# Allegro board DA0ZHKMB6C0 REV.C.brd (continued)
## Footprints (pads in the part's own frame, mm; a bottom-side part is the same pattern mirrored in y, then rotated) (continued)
CC0402
  custom 0.12x0.12 smd: 1(0.39,0) 2(-0.39,0)
CC0603
  rect 0.813x0.711 smd: 1(0.737,0) 2(-0.737,0)
CC0805
  rect 0.94x1.346 smd: 1(0.895,0) 2(-0.895,0)
CC1206
  rect 1.6x1.6 smd: 1(1.702,0) 2(-1.702,0)
CC1808
  rect 2.159x2.286 smd: 1(-2.349,0) 2(2.349,0)
CC3528
  rect 2.032x2.413 smd: 1(1.6,0) 2(-1.6,0)
CC7343
  rect 2.413x2.819 smd: 1(-3.2,0) 2(3.2,0)
CHOKE-DLW21S-4P
  rect 0.889x0.356 smd: 1(-0.85,0.425) 2(0.85,0.425) 3(0.85,-0.425) 4(-0.85,-0.425)
CHOKE-PCMC063T-3R3MN-SMT
  rect 1.854x3.505 smd: 1(-3.275,0) 2(3.275,0)
CHOKE-PCMC063T-R82MN-4P-SMT
  custom 0.591x0.591 smd: 1(-3.596,0) 2(3.596,0)
  rect 1.473x0.305 smd: 3(-2.452,0) 4(2.452,0)
D-DO-214AC
  rect 1.88x2.032 smd: 1(-2.1,0) 2(2.1,0)
DCJK-2DC2003-000111-3P-V
  oval 1.194x2.108 hole 0.61x1.499: 1(4.4,11.25) 3(-4.4,11.25)
  round 2.21 hole 1.499: 2(0,11.25)
  oval 1.194x2.591 hole 0.61x2.007: 4(7,7.9) 5(-7,7.9) 6(7,0) 7(-7,0)
DDR-DDRSK-20401-TP4B-204P-SMT
  round 1.702 hole 1.702 unplated: (-33.4,0)
  round 1.194 hole 1.194 unplated: (33.4,0)
  rect 0.356x2.007 smd: 1(-31.65,-4.1) 2(-31.35,4.1) 3(-31.05,-4.1) 4(-30.75,4.1) 5(-30.45,-4.1) 6(-30.15,4.1) 7(-29.85,-4.1) 8(-29.55,4.1) 9(-29.25,-4.1) 10(-28.95,4.1) 11(-28.65,-4.1) 12(-28.35,4.1) 13(-28.05,-4.1) 14(-27.75,4.1) 15(-27.45,-4.1) 16(-27.15,4.1) 17(-26.85,-4.1) 18(-26.55,4.1) 19(-26.25,-4.1) 20(-25.95,4.1) 21(-25.65,-4.1) 22(-25.35,4.1) 23(-25.05,-4.1) 24(-24.75,4.1) 25(-24.45,-4.1) 26(-24.15,4.1) 27(-23.85,-4.1) 28(-23.55,4.1) 29(-23.25,-4.1) 30(-22.95,4.1) 31(-22.65,-4.1) 32(-22.35,4.1) 33(-22.05,-4.1) 34(-21.75,4.1) 35(-21.45,-4.1) 36(-21.15,4.1) 37(-20.85,-4.1) 38(-20.55,4.1) 39(-20.25,-4.1) 40(-19.95,4.1) 41(-19.65,-4.1) 42(-19.35,4.1) 43(-19.05,-4.1) 44(-18.75,4.1) 45(-18.45,-4.1) 46(-18.15,4.1) 47(-17.85,-4.1) 48(-17.55,4.1) 49(-17.25,-4.1) 50(-16.95,4.1) 51(-16.65,-4.1) 52(-16.35,4.1) 53(-16.05,-4.1) 54(-15.75,4.1) 55(-15.45,-4.1) 56(-15.15,4.1) 57(-14.85,-4.1) 58(-14.55,4.1) 59(-14.25,-4.1) 60(-13.95,4.1) 61(-13.65,-4.1) 62(-13.35,4.1) 63(-13.05,-4.1) 64(-12.75,4.1) 65(-12.45,-4.1) 66(-12.15,4.1) 67(-11.85,-4.1) 68(-11.55,4.1) 69(-11.25,-4.1) 70(-10.95,4.1) 71(-10.65,-4.1) 72(-10.35,4.1) 73(-7.65,-4.1) 74(-7.35,4.1) 75(-7.05,-4.1) 76(-6.75,4.1) 77(-6.45,-4.1) 78(-6.15,4.1) 79(-5.85,-4.1) 80(-5.55,4.1) 81(-5.25,-4.1) 82(-4.95,4.1) 83(-4.65,-4.1) 84(-4.35,4.1) 85(-4.05,-4.1) 86(-3.75,4.1) 87(-3.45,-4.1) 88(-3.15,4.1) 89(-2.85,-4.1) 90(-2.55,4.1) 91(-2.25,-4.1) 92(-1.95,4.1) 93(-1.65,-4.1) 94(-1.35,4.1) 95(-1.05,-4.1) 96(-0.75,4.1) 97(-0.45,-4.1) 98(-0.15,4.1) 99(0.15,-4.1) 100(0.45,4.1) 101(0.75,-4.1) 102(1.05,4.1) 103(1.35,-4.1) 104(1.65,4.1) 105(1.95,-4.1) 106(2.25,4.1) 107(2.55,-4.1) 108(2.85,4.1) 109(3.15,-4.1) 110(3.45,4.1) 111(3.75,-4.1) 112(4.05,4.1) 113(4.35,-4.1) 114(4.65,4.1) 115(4.95,-4.1) 116(5.25,4.1) 117(5.55,-4.1) 118(5.85,4.1) 119(6.15,-4.1) 120(6.45,4.1) 121(6.75,-4.1) 122(7.05,4.1) 123(7.35,-4.1) 124(7.65,4.1) 125(7.95,-4.1) 126(8.25,4.1) 127(8.55,-4.1) 128(8.85,4.1) 129(9.15,-4.1) 130(9.45,4.1) 131(9.75,-4.1) 132(10.05,4.1) 133(10.35,-4.1) 134(10.65,4.1) 135(10.95,-4.1) 136(11.25,4.1) 137(11.55,-4.1) 138(11.85,4.1) 139(12.15,-4.1) 140(12.45,4.1) 141(12.75,-4.1) 142(13.05,4.1) 143(13.35,-4.1) 144(13.65,4.1) 145(13.95,-4.1) 146(14.25,4.1) 147(14.55,-4.1) 148(14.85,4.1) 149(15.15,-4.1) 150(15.45,4.1) 151(15.75,-4.1) 152(16.05,4.1) 153(16.35,-4.1) 154(16.65,4.1) 155(16.95,-4.1) 156(17.25,4.1) 157(17.55,-4.1) 158(17.85,4.1) 159(18.15,-4.1) 160(18.45,4.1) 161(18.75,-4.1) 162(19.05,4.1) 163(19.35,-4.1) 164(19.65,4.1) 165(19.95,-4.1) 166(20.25,4.1) 167(20.55,-4.1) 168(20.85,4.1) 169(21.15,-4.1) 170(21.45,4.1) 171(21.75,-4.1) 172(22.05,4.1) 173(22.35,-4.1) 174(22.65,4.1) 175(22.95,-4.1) 176(23.25,4.1) 177(23.55,-4.1) 178(23.85,4.1) 179(24.15,-4.1) 180(24.45,4.1) 181(24.75,-4.1) 182(25.05,4.1) 183(25.35,-4.1) 184(25.65,4.1) 185(25.95,-4.1) 186(26.25,4.1) 187(26.55,-4.1) 188(26.85,4.1) 189(27.15,-4.1) 190(27.45,4.1) 191(27.75,-4.1) 192(28.05,4.1) 193(28.35,-4.1) 194(28.65,4.1) 195(28.95,-4.1) 196(29.25,4.1) 197(29.55,-4.1) 198(29.85,4.1) 199(30.15,-4.1) 200(30.45,4.1) 201(30.75,-4.1) 202(31.05,4.1) 203(31.35,-4.1) 204(31.65,4.1)
  rect 4.496x4.597 smd: 205(-32.55,12) 206(32.55,12)
DFN10-3X3-5-11P-SYF554DBC
  rect 0.305x0.559 smd: 1(-1,-1.35) 2(-0.5,-1.35) 3(0,-1.35) 4(0.5,-1.35) 5(1,-1.35) 6(1,1.35) 7(0.5,1.35) 8(0,1.35) 9(-0.5,1.35) 10(-1,1.35)
  rect 2.591x1.753 smd: 11(0,0)
DSM
  rect 1.016x0.508 smd: 1(-1.3,0) 2(1.321,0)
ECAP6_3X6_1-7_2
  rect 1.6x3.505 smd: 1(0,-2.8) 2(0,2.8)
F3_2X1_65-2_8
  rect 0.991x1.803 smd: 1(-1.4,0) 2(1.4,0)
H-C51D51N
  round 1.295 hole 1.295 unplated: (0,0)
H-C70D70N
  round 1.778 hole 1.778 unplated: (0,0)
H-C197D140P2
  round 5.004 hole 3.556: 1(0,0)
H-C236D118P2
  round 5.994 hole 2.997: 1(0,0)
H-O39X279D39X279N
  oval 0.991x7.087 hole 0.991x7.087 unplated: (0,0)
H-O39X475D39X475N
  oval 0.991x12.065 hole 0.991x12.065 unplated: (0,0)
H-TC197BC83D83PT
  round 2.108 hole 2.108: 1(0,0)
HDMI-HDM-19DVXB-19P
  round 0.787 hole 0.559: 1(4.5,7.28) 2(4,5.78) 3(3.5,7.28) 4(3,5.78) 5(2.5,7.28) 6(2,5.78) 7(1.5,7.28) 8(1,5.78) 9(0.5,7.28) 10(0,5.78) 11(-0.5,7.28) 12(-1,5.78) 13(-1.5,7.28) 14(-2,5.78) 15(-2.5,7.28) 16(-3,5.78) 17(-3.5,7.28) 18(-4,5.78) 19(-4.5,7.28)
  oval 1.702x2.896 hole 1.092x2.311: 20(7.25,6.48) 22(-7.25,6.48)
  oval 1.702x2.007 hole 1.092x1.397: 21(9.25,0) 23(-9.25,0)
HG-C492D335P2
  round 12.497 hole 8.509: 1(0,0)
  round 1.016 hole 0.61: 2(1.796,4.934) 3(4.759,2.219) 4(4.935,-1.796) 5(2.219,-4.759)
HG-TC256BC354D118P2
  round 6.502 hole 2.997: 1(0,0)
  round 1.016 hole 0.61: 2(0,2.286) 3(1.616,1.616) 4(2.286,0) 5(1.616,-1.616) 6(0,-2.286) 7(-1.616,-1.616) 8(-2.286,0) 9(-1.616,1.616)
HG-TC276BC335D118P2
  round 7.01 hole 2.997: 1(0,0)
  round 1.016 hole 0.61: 2(0,2.286) 3(1.616,1.616) 4(2.286,0) 5(1.616,-1.616) 6(0,-2.286) 7(-1.616,-1.616) 8(-2.286,0) 9(-1.616,1.616)
HG-TC315BC276D118P2
  round 8.001 hole 2.997: 1(0,0)
  round 1.016 hole 0.61: 2(0,2.54) 3(1.796,1.796) 4(2.54,0) 5(1.796,-1.796) 6(0,-2.54) 7(-1.796,-1.796) 8(-2.54,0) 9(-1.796,1.796)
HG-TC394BC236D118P2
  round 10.008 hole 2.997: 1(0,0)
  round 1.016 hole 0.61: 2(0,2.249) 3(1.59,1.59) 4(2.249,0) 5(1.59,-1.59) 6(0,-2.249) 7(-1.59,-1.59) 8(-2.249,0) 9(-1.59,1.59)
L3_2X2_5-1_55
  rect 1.245x2.007 smd: 1(-1.275,0) 2(1.275,0)
L3_2X2_5-3_2
  rect 1.194x2.007 smd: 1(-1.6,0) 2(1.6,0)
LED19-123-Y2ST1D-C30-2T-4P
  rect 1.092x0.61 smd: 1(0.95,0.45) 2(0.95,-0.45) 3(-0.95,-0.45) 4(-0.95,0.45)
LQFP128-16X16-4
  rect 0.203x1.499 smd: 1(-6.2,-7.85) 2(-5.8,-7.85) 3(-5.4,-7.85) 4(-5,-7.85) 5(-4.6,-7.85) 6(-4.2,-7.85) 7(-3.8,-7.85) 8(-3.4,-7.85) 9(-3,-7.85) 10(-2.6,-7.85) 11(-2.2,-7.85) 12(-1.8,-7.85) 13(-1.4,-7.85) 14(-1,-7.85) 15(-0.6,-7.85) 16(-0.2,-7.85) 17(0.2,-7.85) 18(0.6,-7.85) 19(1,-7.85) 20(1.4,-7.85) 21(1.8,-7.85) 22(2.2,-7.85) 23(2.6,-7.85) 24(3,-7.85) 25(3.4,-7.85) 26(3.8,-7.85) 27(4.2,-7.85) 28(4.6,-7.85) 29(5,-7.85) 30(5.4,-7.85) 31(5.8,-7.85) 32(6.2,-7.85) 65(6.2,7.85) 66(5.8,7.85) 67(5.4,7.85) 68(5,7.85) 69(4.6,7.85) 70(4.2,7.85) 71(3.8,7.85) 72(3.4,7.85) 73(3,7.85) 74(2.6,7.85) 75(2.2,7.85) 76(1.8,7.85) 77(1.4,7.85) 78(1,7.85) 79(0.6,7.85) 80(0.2,7.85) 81(-0.2,7.85) 82(-0.6,7.85) 83(-1,7.85) 84(-1.4,7.85) 85(-1.8,7.85) 86(-2.2,7.85) 87(-2.6,7.85) 88(-3,7.85) 89(-3.4,7.85) 90(-3.8,7.85) 91(-4.2,7.85) 92(-4.6,7.85) 93(-5,7.85) 94(-5.4,7.85) 95(-5.8,7.85) 96(-6.2,7.85)
  rect 1.499x0.203 smd: 33(7.85,-6.2) 34(7.85,-5.8) 35(7.85,-5.4) 36(7.85,-5) 37(7.85,-4.6) 38(7.85,-4.2) 39(7.85,-3.8) 40(7.85,-3.4) 41(7.85,-3) 42(7.85,-2.6) 43(7.85,-2.2) 44(7.85,-1.8) 45(7.85,-1.4) 46(7.85,-1) 47(7.85,-0.6) 48(7.85,-0.2) 49(7.85,0.2) 50(7.85,0.6) 51(7.85,1) 52(7.85,1.4) 53(7.85,1.8) 54(7.85,2.2) 55(7.85,2.6) 56(7.85,3) 57(7.85,3.4) 58(7.85,3.8) 59(7.85,4.2) 60(7.85,4.6) 61(7.85,5) 62(7.85,5.4) 63(7.85,5.8) 64(7.85,6.2) 97(-7.85,6.2) 98(-7.85,5.8) 99(-7.85,5.4) 100(-7.85,5) 101(-7.85,4.6) 102(-7.85,4.2) 103(-7.85,3.8) 104(-7.85,3.4) 105(-7.85,3) 106(-7.85,2.6) 107(-7.85,2.2) 108(-7.85,1.8) 109(-7.85,1.4) 110(-7.85,1) 111(-7.85,0.6) 112(-7.85,0.2) 113(-7.85,-0.2) 114(-7.85,-0.6) 115(-7.85,-1) 116(-7.85,-1.4) 117(-7.85,-1.8) 118(-7.85,-2.2) 119(-7.85,-2.6) 120(-7.85,-3) 121(-7.85,-3.4) 122(-7.85,-3.8) 123(-7.85,-4.2) 124(-7.85,-4.6) 125(-7.85,-5) 126(-7.85,-5.4) 127(-7.85,-5.8) 128(-7.85,-6.2)
MIC-FM-M201-U03-6P
  round 0.991 smd: 1(-1.17,1.65) 2(-1.17,0) 3(-1.17,-1.65) 4(1.17,-1.65) 5(1.17,0)
  oval 0.991x1.295 smd rot 135: 6(1.065,1.55)
MINIPCI-80053-1023-52P-SMT
  round 1.6 hole 1.6 unplated: (-12.5,0) (12.5,0)
  oval 0.61x0.864 hole 0.406x0.61: 1(-11.8,-2.3) 3(-11,-2.3) 5(-10.2,-2.3) 7(-9.4,-2.3) 9(-8.6,-2.3) 11(-7.8,-2.3) 13(-7,-2.3) 15(-6.2,-2.3) 17(-2.2,-2.3) 19(-1.4,-2.3) 21(-0.6,-2.3) 23(0.2,-2.3) 25(1,-2.3) 27(1.8,-2.3) 29(2.6,-2.3) 31(3.4,-2.3) 33(4.2,-2.3) 35(5,-2.3) 37(5.8,-2.3) 39(6.6,-2.3) 41(7.4,-2.3) 43(8.2,-2.3) 45(9,-2.3) 47(9.8,-2.3) 49(10.6,-2.3) 51(11.4,-2.3)
  rect 0.508x2.007 smd: 2(-11.4,3.23) 4(-10.6,3.23) 6(-9.8,3.23) 8(-9,3.23) 10(-8.2,3.23) 12(-7.4,3.23) 14(-6.6,3.23) 16(-5.8,3.23) 18(-1.8,3.23) 20(-1,3.23) 22(-0.2,3.23) 24(0.6,3.23) 26(1.4,3.23) 28(2.2,3.23) 30(3,3.23) 32(3.8,3.23) 34(4.6,3.23) 36(5.4,3.23) 38(6.2,3.23) 40(7,3.23) 42(7.8,3.23) 44(8.6,3.23) 46(9.4,3.23) 48(10.2,3.23) 50(11,3.23) 52(11.8,3.23)
  rect 2.311x3.2 smd: 53(-14.94,-1.55) 54(14.94,-1.55)
ML1220-SMT
  round 1.092 hole 1.092 unplated: (0,3.988)
  round 0.711 hole 0.711 unplated: (0,-3.988)
  rect 2.997x1.499 smd: 1(-7.391,0) 2(7.391,0)
MSC-RB30-5-FG-30P-L-SMT
  round 1.295 hole 1.295 unplated: (-10.55,0) (10.55,0)
  rect 0.406x1.549 smd: 1(-8.25,1.925) 2(-7.25,1.925) 3(-6.25,1.925) 4(-5.25,1.925)
  rect 0.279x1.549 smd: 5(-4.25,1.925) 6(-3.75,1.925) 7(-3.25,1.925) 8(-2.75,1.925) 9(-2.25,1.925) 10(-1.75,1.925) 11(-1.25,1.925) 12(-0.75,1.925) 13(-0.25,1.925) 14(0.25,1.925) 15(0.75,1.925) 16(1.25,1.925) 17(1.75,1.925) 18(2.25,1.925) 19(2.75,1.925) 20(3.25,1.925) 21(3.75,1.925) 22(4.25,1.925) 23(4.75,1.925) 24(5.25,1.925) 25(5.75,1.925) 26(6.25,1.925) 27(6.75,1.925) 28(7.25,1.925) 29(7.75,1.925) 30(8.25,1.925)
  rect 1.956x3.404 smd: 31(-12.175,-3.8) 34(12.175,-3.8)
  rect 2.591x2.108 smd: 32(-7.25,-4.45) 33(7.25,-4.45)
MSOP8-4_9-65
  rect 0.406x1.448 smd: 1(-0.975,-2.325) 2(-0.325,-2.325) 3(0.325,-2.325) 4(0.975,-2.325) 5(0.975,2.325) 6(0.325,2.325) 7(-0.325,2.325) 8(-0.975,2.325)
O-ZHJ-9
  custom 1.875x1.875 hole 2.997: 1(0,0)
  round 1.016 hole 0.61: 2(0,2.286) 3(1.616,1.616) 4(2.286,0) 5(1.616,-1.616) 6(0,-2.286) 7(-1.616,-1.616) 8(-2.286,0) 9(-1.616,1.616)
  round 3.708 hole 2.692: 10(0,6)
O-ZHJ-21
  rect 12.7x7.823 hole 2.794: 1(0,0)
  round 1.016 hole 0.61: 2(0,2.032) 3(1.437,1.437) 4(2.032,0) 5(1.437,-1.437) 6(0,-2.032) 7(-1.437,-1.437) 8(-2.032,0) 9(-1.437,1.437)
PHJK-2SJ3072-108111F-6P
  round 1.397 hole 1.397 unplated: (0,6.5) (0,0)
  oval 0.991x1.702 hole 0.61x1.295: 1(-2.85,9.6) 2(2.7,2.15) 3(-2.7,1.3) 4(3.35,0.1) 5(2.15,9.6) 6(2.75,7.4) 7(-3.6,4.8) 8(3.6,4.8)
POWER-5X6-1_27-7P
  rect 0.635x0.66 smd: 1(2.835,-1.905) 5(-2.835,1.905) 6(-2.835,0.635) 7(-2.835,-0.635) 8(-2.835,-1.905)
  custom 0.485x0.485 smd: 2(2.18,0.115)
  rect 2.159x3.988 smd: 9(-0.525,0)
QFN14-3X3-4-16P
  rect 1.092x0.203 smd: 1(-1.25,0.525) 2(-1.25,-0.175) 8(1.25,-0.525) 9(1.25,0.175)
  rect 0.203x0.711 smd: 3(-0.8,-1.45) 4(-0.4,-1.45) 5(0,-1.45) 6(0.4,-1.45) 7(0.8,-1.45) 10(0.8,1.45) 11(0.4,1.45) 12(0,1.45) 13(-0.4,1.45) 14(-0.8,1.45)
  rect 0.66x0.203 smd: 15(0,0.165) 16(0,-0.435)
QFN28-5X5-5-29P-GL850G
  rect 0.991x0.305 smd: 1(-2.6,1.5) 2(-2.6,1) 3(-2.6,0.5) 4(-2.6,0) 5(-2.6,-0.5) 6(-2.6,-1) 7(-2.6,-1.5) 15(2.6,-1.5) 16(2.6,-1) 17(2.6,-0.5) 18(2.6,0) 19(2.6,0.5) 20(2.6,1) 21(2.6,1.5)
  rect 0.305x0.991 smd: 8(-1.5,-2.6) 9(-1,-2.6) 10(-0.5,-2.6) 11(0,-2.6) 12(0.5,-2.6) 13(1,-2.6) 14(1.5,-2.6) 22(1.5,2.6) 23(1,2.6) 24(0.5,2.6) 25(0,2.6) 26(-0.5,2.6) 27(-1,2.6) 28(-1.5,2.6)
  rect 3.505x3.505 smd: 29(0,0)
QFN32-4X4-4-33P-0_9H
  custom 0.051x0.051 smd: 1(-1.4,-2.1) 8(1.4,-2.1) 9(2.1,-1.4) 16(2.1,1.4) 17(1.4,2.1) 24(-1.4,2.1) 25(-2.1,1.4) 32(-2.1,-1.4)
  rect 0.203x0.991 smd: 2(-1,-2.1) 3(-0.6,-2.1) 4(-0.2,-2.1) 5(0.2,-2.1) 6(0.6,-2.1) 7(1,-2.1) 18(1,2.1) 19(0.6,2.1) 20(0.2,2.1) 21(-0.2,2.1) 22(-0.6,2.1) 23(-1,2.1)
  rect 0.991x0.203 smd: 10(2.1,-1) 11(2.1,-0.6) 12(2.1,-0.2) 13(2.1,0.2) 14(2.1,0.6) 15(2.1,1) 26(-2.1,1) 27(-2.1,0.6) 28(-2.1,0.2) 29(-2.1,-0.2) 30(-2.1,-0.6) 31(-2.1,-1)
  rect 2.692x2.692 smd: 33(0,0)
QFN32-4X4-4-33P-ISL95812HRZ-SMT
  custom 0.05x0.05 smd: 1(-1.4,-2) 8(1.4,-2) 9(2,-1.4) 16(2,1.4) 17(1.4,2) 24(-1.4,2) 25(-2,1.4) 32(-2,-1.4)
  rect 0.203x0.787 smd: 2(-1,-2) 3(-0.6,-2) 4(-0.2,-2) 5(0.2,-2) 6(0.6,-2) 7(1,-2) 18(1,2) 19(0.6,2) 20(0.2,2) 21(-0.2,2) 22(-0.6,2) 23(-1,2)
  rect 0.787x0.203 smd: 10(2,-1) 11(2,-0.6) 12(2,-0.2) 13(2,0.2) 14(2,0.6) 15(2,1) 26(-2,1) 27(-2,0.6) 28(-2,0.2) 29(-2,-0.2) 30(-2,-0.6) 31(-2,-1)
  rect 2.642x2.642 smd: 33(0,0)
QFN48-6X6-4-49P-ALC280
  rect 0.203x0.991 smd: 1(-2.2,-3.1) 2(-1.8,-3.1) 3(-1.4,-3.1) 4(-1,-3.1) 5(-0.6,-3.1) 6(-0.2,-3.1) 7(0.2,-3.1) 8(0.6,-3.1) 9(1,-3.1) 10(1.4,-3.1) 11(1.8,-3.1) 12(2.2,-3.1) 25(2.2,3.1) 26(1.8,3.1) 27(1.4,3.1) 28(1,3.1) 29(0.6,3.1) 30(0.2,3.1) 31(-0.2,3.1) 32(-0.6,3.1) 33(-1,3.1) 34(-1.4,3.1) 35(-1.8,3.1) 36(-2.2,3.1)
  rect 0.991x0.203 smd: 13(3.1,-2.2) 14(3.1,-1.8) 15(3.1,-1.4) 16(3.1,-1) 17(3.1,-0.6) 18(3.1,-0.2) 19(3.1,0.2) 20(3.1,0.6) 21(3.1,1) 22(3.1,1.4) 23(3.1,1.8) 24(3.1,2.2) 37(-3.1,2.2) 38(-3.1,1.8) 39(-3.1,1.4) 40(-3.1,1) 41(-3.1,0.6) 42(-3.1,0.2) 43(-3.1,-0.2) 44(-3.1,-0.6) 45(-3.1,-1) 46(-3.1,-1.4) 47(-3.1,-1.8) 48(-3.1,-2.2)
  rect 4.394x4.394 smd: 49(0,0)
RC0402
  custom 0.12x0.12 smd: 1(0.39,0) 2(-0.39,0)
RC0603
  rect 0.813x0.711 smd: 1(0.737,0) 2(-0.737,0)
RC0805
  rect 0.94x1.346 smd: 1(0.895,0) 2(-0.895,0)
RJ45-C100MP-10809-L-8P
  round 1.194 hole 0.889: 1(-3.556,3.15) 2(-2.54,4.25) 3(-1.524,3.15) 4(-0.508,4.25) 5(0.508,3.15) 6(1.524,4.25) 7(2.54,3.15) 8(3.556,4.25)
  oval 0.889x2.311 hole 0.61x2.007: 9(-8,-6.6) 10(-8,0) 11(8,-6.6) 12(8,0)
SATA-C166KN-12209-L-22P-L-SMT
  round 1.118 hole 1.118 unplated: (-18.71,0)
  round 1.499 hole 1.499 unplated: (18.71,0)
  round 1.067 hole 0.711: 1(-15.875,0) 2(-14.605,0) 3(-13.335,0) 4(-12.065,0) 5(-10.795,0) 6(-9.525,0) 7(-8.255,0) 8(-1.905,0) 9(-0.635,0) 10(0.635,0) 11(1.905,0) 12(3.175,0) 13(4.445,0) 14(5.715,0) 15(6.985,0) 16(8.255,0) 17(9.525,0) 18(10.795,0) 19(12.065,0) 20(13.335,0) 21(14.605,0) 22(15.875,0)
  round 3.124 hole 2.108: 23(-22,-0.71) 24(22,-0.71)
SC70-2_1-65-6P
  rect 1.27x0.279 smd: 1(1.02,-0.65) 2(1.02,0) 3(1.02,0.65) 4(-1.02,0.65) 5(-1.02,0) 6(-1.02,-0.65)
SC70-2_1-65-6P-0_95H
  rect 0.508x0.406 smd: 1(0.95,-0.65) 2(0.95,0) 3(0.95,0.65) 4(-0.95,0.65) 5(-0.95,0) 6(-0.95,-0.65)
SDCARD-CS1S-441-H-N-11P
  round 1.092 hole 1.092 unplated: (-11.2,0)
  round 1.6 hole 1.6 unplated: (10.8,0)
  rect 0.787x1.194 smd: 1(6.92,4.6) 2(4.42,4.6) 3(1.92,4.6) 4(-0.58,4.6) 5(-3.08,4.6) 6(-5.58,4.6) 7(-8,4.6) 8(-9.7,4.6) 9(9.42,4.6)
  rect 1.905x1.6 smd: 10(-13.17,2.35)
  rect 1.499x1.702 smd: 11(-13.39,-4.3)
  rect 1.194x2.311 smd: 12(-13.75,-8.75) 13(13.75,-8.75)
SHORT0402
  rect 0.648x0.5 smd: 1(-0.39,0) 2(0.39,0)
SHORT0603
  rect 1.168x0.711 smd: 1(0.737,0) 2(-0.737,0)
SHORT0805
  rect 1.397x1.346 smd: 1(0.895,0) 2(-0.895,0)
SOIC8-6-1_27
  rect 0.533x1.753 smd: 1(-1.905,-2.73) 2(-0.635,-2.73) 3(0.635,-2.73) 4(1.905,-2.73) 5(1.905,2.73) 6(0.635,2.73) 7(-0.635,2.73) 8(-1.905,2.73)
SOIC8-7_9-1_27
  rect 0.533x1.549 smd: 1(-1.905,-3.775) 2(-0.635,-3.775) 3(0.635,-3.775) 4(1.905,-3.775) 5(1.905,3.775) 6(0.635,3.775) 7(-0.635,3.775) 8(-1.905,3.775)
SOLDERJUMPER-2
  custom 0.381x0.381 smd: 1(-1.016,0) 2(1.016,0)
SOP8-6-1_27-9P
  rect 0.533x1.727 smd: 1(-1.905,-2.73) 2(-0.635,-2.73) 3(0.635,-2.73) 4(1.905,-2.73) 5(1.905,2.73) 6(0.635,2.73) 7(-0.635,2.73) 8(-1.905,2.73)
  rect 3.302x2.794 smd: 9(0,0)
SOT23-2_8-95-6P
  rect 1.346x0.508 smd: 1(1.325,-0.95) 2(1.325,0) 3(1.325,0.95) 4(-1.325,0.95) 5(-1.325,0) 6(-1.325,-0.95)
SOT23-5-2_8-95-5P-1_3H
  rect 1.194x0.533 smd: 1(1.5,-0.95) 2(1.5,0) 3(1.5,0.95) 4(-1.5,0.95) 5(-1.5,-0.95)
SOT23_123-2_8-1_9
  rect 1.092x0.533 smd: 1(1.45,-0.95) 2(1.45,0.95) 3(-1.45,0)
SOT23_213-3_3-2
  rect 1.27x1.016 smd: 1(1.016,1.016) 2(1.016,-1.016) 3(-1.016,0)
SOT323_213-2_1-1_3-2N7002W
  rect 0.787x0.61 smd: 1(0.8,0.65) 2(0.8,-0.65) 3(-0.8,0)
SW-NTC031-AB1G-A160T-4P
  rect 1.092x1.092 smd: 1(-1.85,3.05) 2(1.85,3.05) 3(-1.85,-3.05) 4(1.85,-3.05)
  rect 0.559x0.991 smd: 5(-2.575,0) 6(2.575,0)
TO252_134-9_9-4_57-SMT
  rect 2.997x1.499 smd: 1(8.1,-2.286) 3(8.1,2.286)
  rect 5.613x6.248 smd: 4(0.6,0)
TP2050
  round 0.508 smd: 1(0,0)
TP2650
  round 0.66 smd: 1(0,0)
TP2675
  round 0.66 smd: 1(0,0)
TQFN20-3X3-4-21P
  rect 0.711x0.203 smd: 1(-1.5,0.8) 2(-1.5,0.4) 3(-1.5,0) 4(-1.5,-0.4) 5(-1.5,-0.8) 11(1.5,-0.8) 12(1.5,-0.4) 13(1.5,0) 14(1.5,0.4) 15(1.5,0.8)
  rect 0.203x0.711 smd: 6(-0.8,-1.5) 7(-0.4,-1.5) 8(0,-1.5) 9(0.4,-1.5) 10(0.8,-1.5) 16(0.8,1.5) 17(0.4,1.5) 18(0,1.5) 19(-0.4,1.5) 20(-0.8,1.5)
  rect 1.499x1.499 smd: 21(0,0)
TRF-9_4-1_27-24P
  rect 0.762x1.219 smd: 1(-6.985,-4.35) 2(-5.715,-4.35) 3(-4.445,-4.35) 4(-3.175,-4.35) 5(-1.905,-4.35) 6(-0.635,-4.35) 7(0.635,-4.35) 8(1.905,-4.35) 9(3.175,-4.35) 10(4.445,-4.35) 11(5.715,-4.35) 12(6.985,-4.35) 13(6.985,4.35) 14(5.715,4.35) 15(4.445,4.35) 16(3.175,4.35) 17(1.905,4.35) 18(0.635,4.35) 19(-0.635,4.35) 20(-1.905,4.35) 21(-3.175,4.35) 22(-4.445,4.35) 23(-5.715,4.35) 24(-6.985,4.35)
TSOP6-2_8-95
  rect 0.787x0.635 smd: 1(1.2,-0.95) 2(1.2,0) 3(1.2,0.95) 4(-1.2,0.95) 5(-1.2,0) 6(-1.2,-0.95)
TSSOP28-6_4-65-SLB9635TT
  rect 0.406x1.295 smd: 1(-4.225,-3.05) 2(-3.575,-3.05) 3(-2.925,-3.05) 4(-2.275,-3.05) 5(-1.625,-3.05) 6(-0.975,-3.05) 7(-0.325,-3.05) 8(0.325,-3.05) 9(0.975,-3.05) 10(1.625,-3.05) 11(2.275,-3.05) 12(2.925,-3.05) 13(3.575,-3.05) 14(4.225,-3.05) 15(4.225,3.05) 16(3.575,3.05) 17(2.925,3.05) 18(2.275,3.05) 19(1.625,3.05) 20(0.975,3.05) 21(0.325,3.05) 22(-0.325,3.05) 23(-0.975,3.05) 24(-1.625,3.05) 25(-2.275,3.05) 26(-2.925,3.05) 27(-3.575,3.05) 28(-4.225,3.05)
UMT_213-3-1_3
  rect 1.016x0.762 smd: 1(0.991,0.66) 2(0.991,-0.66) 3(-0.991,0)
unnamed
  round 1.016 smd: 1(0,0)
USB-020133GR004M22BZL-4P
  round 1.524 hole 0.914: 1(-3.5,7.65) 2(-1,7.65) 3(1,7.65) 4(3.5,7.65)
  oval 1.499x2.997 hole 0.889x2.388: 5(-7.85,6.8) 6(7.85,6.8)
  oval 1.194x2.007 hole 0.61x1.397: 7(-7.85,0) 8(7.85,0)
USB-53063-00902-001-9P-SMT
  round 1.118 hole 0.813: 1(-3.5,7.73) 2(-1,7.73) 3(1,7.73) 4(3.5,7.73) 5(4,9.23) 6(2,9.23) 7(0,9.23) 8(-2,9.23) 9(-4,9.23)
  oval 1.626x2.515 hole 0.61x1.499: 10(-7.85,0) 11(7.85,0)
  oval 1.727x3.327 hole 0.711x2.311: 12(7.85,6.8) 13(-7.85,6.8)
VQFN40-5X5-4-57P
  rect 0.991x0.203 smd: 1(-2.6,1.8) 2(-2.6,1.4) 3(-2.6,1) 4(-2.6,0.6) 5(-2.6,0.2) 6(-2.6,-0.2) 7(-2.6,-0.6) 8(-2.6,-1) 9(-2.6,-1.4) 10(-2.6,-1.8) 21(2.6,-1.8) 22(2.6,-1.4) 23(2.6,-1) 24(2.6,-0.6) 25(2.6,-0.2) 26(2.6,0.2) 27(2.6,0.6) 28(2.6,1) 29(2.6,1.4) 30(2.6,1.8)
  rect 0.203x0.991 smd: 11(-1.8,-2.6) 12(-1.4,-2.6) 13(-1,-2.6) 14(-0.6,-2.6) 15(-0.2,-2.6) 16(0.2,-2.6) 17(0.6,-2.6) 18(1,-2.6) 19(1.4,-2.6) 20(1.8,-2.6) 31(1.8,2.6) 32(1.4,2.6) 33(1,2.6) 34(0.6,2.6) 35(0.2,2.6) 36(-0.2,2.6) 37(-0.6,2.6) 38(-1,2.6) 39(-1.4,2.6) 40(-1.8,2.6)
  rect 1.168x1.575 smd: 41(1.21,1.01)
  rect 1.981x1.575 smd: 42(-0.81,1.01)
  rect 3.607x1.575 smd: 43(0,-1.01)
  round 0.61 hole 0.305: 44(-1.242,1.404) 45(-1.242,0.616) 46(-1.301,-0.616) 47(-1.301,-1.404) 48(-0.434,-1.404) 49(0.434,-1.404) 50(1.301,-1.404) 51(1.301,-0.616) 52(1.21,0.616) 53(1.21,1.404) 54(-0.378,1.404) 55(-0.378,0.616) 56(-0.434,-0.616) 57(0.434,-0.616)
VSSOP8-3_1-5-8P
  rect 0.203x1.168 smd: 1(-0.75,-1.563) 2(-0.25,-1.563) 3(0.25,-1.563) 4(0.75,-1.563) 5(0.75,1.563) 6(0.25,1.563) 7(-0.25,1.563) 8(-0.75,1.563)
WDFN5-3_05X3_05-65
  rect 0.66x0.432 smd: 1(1.385,-0.975) 2(1.385,-0.325) 3(1.385,0.325) 4(1.385,0.975)
  custom 0.575x0.575 smd: 5(-0.735,0)
XTL-3_2X1_5-2_5-0_8H
  rect 0.991x1.803 smd: 1(-1.25,0) 2(1.25,0)
XTL-3_2X2_5-2_2X1_7
  rect 1.397x1.194 smd: 1(-1.1,-0.85) 2(1.1,-0.85) 3(1.1,0.85) 4(-1.1,0.85)
XTL-3_2X2_5-2_2X1_8-4P
  rect 1.397x1.194 smd: 1(-1.1,-0.9) 2(1.1,-0.9) 3(1.1,0.9) 4(-1.1,0.9)

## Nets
2.469V: PR171.1 PR172.2 PU15.3
5V_HSMBCK: D10.1 R14.1
5V_HSMBDT: D9.1 R11.1
5VUSB_0: C20.2 C21.2 C145.1 C148.2 C149.2 CN6.1 CN8.1 U19.1
51216VBST: PR51.2 PU9.15
51216VBST_S: PC71.1 PR51.1
51216VDDQSNS: PR161.1 PU9.9
+1.0V: C161.1 C162.2 C173.2 C174.2 C188.2 C189.2 C194.2 C197.1 C208.2 C215.1 C216.1 C217.2 C243.2 PC21.1 PC23.1 PC103.1 PQ14.1 PR96.1 PR99.1 PR101.1 PR104.1 PR108.1 R127.2 R128.1 R148.1 R149.1 U12.AF16 U12.AF18 U12.AK18 U12.AM18 U12.AM21 U12.AN18 U12.AN19 U12.AN21 U12.AN25 U12.BJ6 U12.G1 U12.M14 U12.U18 U12.U19 U12.V32 U12.Y18
+1.0V_S5: PC37.1 PC40.2 PC129.2 PC142.2 PL9.2 PQ14.3 PR114.2 R238.1 R240.2
+1.0VSX: PC139.1 R148.2 R149.2 R309.1 R325.1 R331.1 R335.1
+1.5V: C51.1 C52.1 C69.1 C70.1 C254.2 PC161.1 PC162.1 PC167.2 PR150.1 PU14.5 PU14.6 Q11.2 R297.2 U9.9 U9.40 U12.AM32
+1.05V: PC147.2 PC148.1 PC149.1 PL14.2 PR141.2 R332.2 R333.1
+1.05V_VTT_EC: R372.2 U18.12
+1.8V: C339.2 PC114.1 PC115.1 PC200.2 PQ11.1 PQ31.1 PR135.1 Q6.2 Q6.5 Q8.2 Q12.2 Q19.2 Q29.2 Q29.5 Q30.2 Q40.2 Q40.5 R15.1 R28.1 R73.1 R74.1 R79.1 R80.1 R84.1 R118.1 R119.1 R140.2 R145.2 R147.1 R155.2 R156.2 R165.2 R186.2 R206.2 R218.1 R219.1 R237.1 R239.1 R242.1 R243.2 R246.1 R253.1 R260.2 R265.1 R269.1 R292.1 R303.2 R307.1 R317.1 R321.2 R326.2 R419.1 U24.1 U27.2
+1.8V_CARD: PQ30.3 PQ31.3
+1.8V_EMMC: C34.2 C275.2 C276.2 C278.1 C279.1 R326.1 U30.AA3 U30.AA5 U30.K6 U30.W4 U30.Y4
+1.8V_S5: C238.2 PC121.1 PC122.1 PQ13.1 Q18.2 Q21.2 Q21.5 Q23.2 Q23.5 R41.1 R44.1 R48.2 R60.2 R61.2 R63.2 R81.2 R85.1 R88.2 R104.2 R105.2 R244.2 R251.2 R256.2 R259.2 R267.2 R280.2 R282.2 R289.2 R291.1 R295.1 R301.1 R305.1 R318.1 R319.1 R513.2 R550.2 U22.8
+1.8VPCU: PC33.2 PC35.1 PC116.2 PC132.2 PL8.2 PQ11.3 PQ13.3 PR26.2 R245.2 R268.2 R357.1
+1.8VREF: PC59.1 PR158.1 PU9.6
+1.35V: C42.2 C43.2 C44.1 PC164.1 PC166.1 PQ28.1 PR127.1 R340.1 R341.1 R346.1 U12.AG18 U12.AJ19 U12.BD1
+1.35VSUS: C115.1 C271.2 C277.2 C292.2 C293.2 C294.1 C295.2 C298.1 C299.1 C300.1 C301.1 C304.1 C308.1 C309.1 C310.1 C319.1 C320.1 C322.1 C323.1 C324.1 C325.1 C326.1 C327.1 JDIM6.75 JDIM6.76 JDIM6.81 JDIM6.82 JDIM6.87 JDIM6.88 JDIM6.93 JDIM6.94 JDIM6.99 JDIM6.100 JDIM6.105 JDIM6.106 JDIM6.111 JDIM6.112 JDIM6.117 JDIM6.118 JDIM6.123 JDIM6.124 PC54.1 PC86.1 PC92.1 PC158.2 PC169.2 PL13.2 PQ28.3 PR161.2 PU9.2 R323.2 R328.2 R334.2 R344.1 R388.1 R397.1 U12.A48 U12.AK38 U12.AM38 U12.AV41 U12.AV42 U12.BB46 U12.BD49 U12.BD52 U12.BD53 U12.BF44 U12.BG51 U12.BJ48 U12.C51 U12.D44 U12.F49 U12.F52 U12.F53 U12.H46 U12.M41 U12.M42 U12.V38 U12.Y38
+1.35VSUS_VSM: C267.1 C270.1 R334.1 U12.AD38 U12.AF38
+1.35VSX: C191.1 C219.1 C257.2 C263.1 C264.1 PC157.1 R340.2 R341.2 R346.2 U12.AA25 U12.AD36 U12.AF19 U12.AG19 U12.AG32 U12.U36 U12.V36
+3V: C38.1 C59.1 C61.1 C62.1 C89.1 C314.1 C315.1 JDIM6.199 L1.2 PC127.1 PC135.1 PC204.2 PQ2.1 PQ16.1 PQ16.2 PQ16.3 PQ29.3 PR90.2 PR175.1 Q15.2 R24.2 R31.1 R62.2 R67.2 R71.1 R101.2 R122.2 R153.2 R161.2 R167.2 R178.1 R184.1 R185.1 R207.1 R221.1 R222.2 R223.2 R230.2 R231.1 R232.2 R235.2 R275.2 R300.1 R302.2 R304.2 R330.1 R350.2 R370.2 R385.1 R395.2 R398.1 R427.2 R521.2 U7.1 U9.1 U9.36 U21.4 U21.6 U24.6
+3V3_SD_SW: C147.1 C157.2 CN4.4 PQ2.3 R233.2
+3V_EMMC: C4.2 C5.1 C30.2 C60.1 C75.2 R350.1 U30.M6 U30.N5 U30.T10 U30.U9
+3V_HDD: C340.1 C341.1 CN14.8 CN14.9 CN14.10 R427.1
+3V_LDO: PC44.2 PR41.2 PU8.6
+3V_MINI1_VDD: C140.2 C141.2 C142.2 C143.1 CN10.2 CN10.24 CN10.39 CN10.41 CN10.52 R196.2 R203.2 R207.2
+3V_RTC: C335.1 D36.3 R288.2 R413.1 R415.1
+3V_S5: PC120.1 PC130.1 PC168.2 PC170.1 PQ17.1 PR79.1 PR112.1 PR132.1 PR183.1 PU14.3 Q16.2 Q16.5 Q20.2 Q25.2 R159.2 R160.1 R162.1 R164.1 R198.2 R241.1 R257.1 R266.1 R313.1 R338.1 R364.1 R382.2 R411.1 R528.1 R551.2 U26.5
+3V_USB: C87.2 C90.2 C92.2 C94.2 C222.2 C223.2 C258.2 C268.2 R112.2 R113.2 R115.2 R133.2 R144.2 R159.1 R161.1 R306.2 R367.2 U13.5 U13.9 U13.14 U13.21 U13.28
+3VPCU: D36.2 LED7.1 LED7.2 PC50.1 PC52.1 PC55.1 PC58.1 PC60.1 PC74.1 PC145.2 PC146.2 PC198.1 PL11.2 PQ16.5 PQ17.3 PQ38.3 PR23.2 PR36.1 PR42.2 PR174.2 R35.2 R197.2 R345.2 R359.1 R361.2 R366.2 R371.1 R376.1 R378.2 R383.2 R384.2 R386.2 R391.2 R394.2 R522.1 R536.2 RP6.5 RP6.10
+3VPCU_EC: C102.1 C108.1 C125.1 C288.1 C290.2 C296.1 L18.1 R376.2 U18.19 U18.46 U18.76 U18.115
+5V: C71.1 C72.1 D9.2 D10.2 L10.1 PC184.1 PC185.1 PQ34.1 PQ34.2 PQ34.3 PR125.1 PR176.2 Q17.3 R82.1 R294.2 R402.2 U9.41 U9.46
+5V_HDD: C131.1 C132.1 C133.1 C134.1 C135.1 CN14.14 CN14.15 CN14.16 R402.1
+5V_S5: C146.2 PC45.1 PC46.1 PC51.1 PC64.1 PC65.1 PC66.1 PC69.1 PC159.1 PC178.2 PL10.2 PQ34.5 PR11.2 PR12.1 PR22.2 PR107.1 PR144.2 PU9.12 PU10.7 PU14.4 R416.1 R417.1 U19.5
+5VA: C36.1 C39.1 L10.2 U9.26
+12VALW: PC189.1 PR103.1 PR113.1 PR134.1 PU16.13 R187.1 R356.1
+A3VPCU: C103.1 C109.1 L18.2 U18.102
+VCC_CORE: C159.1 C160.2 C167.2 C175.2 C176.2 C178.2 C179.2 C230.2 C231.2 C237.2 PC14.1 PC96.1 PC97.1 PL7.2 PR102.2 R296.1 U12.AA27 U12.AA29 U12.AA30 U12.AC27 U12.AC29 U12.AC30 U12.AD27 U12.AD29 U12.AD30 U12.AF27 U12.AF29 U12.AG27 U12.AG29 U12.AG30 U12.P26 U12.P27 U12.U27 U12.U29 U12.V27 U12.V29 U12.V30 U12.Y27 U12.Y29 U12.Y30
+VCC_GFX: C50.1 C58.1 C151.2 C158.2 C159.2 C160.1 C214.2 C218.2 C229.2 C234.2 C244.2 PC7.1 PC8.1 PC9.1 PL6.2 PR76.2 R236.1 U12.AA24 U12.AC22 U12.AC24 U12.AD22 U12.AD24 U12.AF22 U12.AF24 U12.AG22 U12.AG24 U12.AJ22 U12.AJ24 U12.AK22 U12.AK24 U12.AK25 U12.AK27 U12.AK29 U12.AK30 U12.AK32 U12.AM22
+VDDQ: PC56.1 PR43.1 R396.1 R401.2
+VDDQ_VTT: C303.1 C307.1 C311.1 C316.1 C317.1 JDIM6.203 JDIM6.204 PC53.1 PU9.1 PU9.3
+VIN: C127.1 C128.2 C333.2 C351.1 PC6.1 PC10.2 PC12.2 PC13.1 PC15.2 PC17.2 PC32.1 PC41.2 PC42.2 PC70.2 PC72.2 PC73.2 PC75.2 PC77.1 PC79.1 PC80.1 PC94.1 PC106.1 PC107.1 PC150.1 PC153.1 PC160.1 PC175.1 PC177.1 PC179.1 PC180.1 PC186.1 PD10.2 PQ6.2 PQ7.2 PQ9.5 PR39.1 PR118.1 PR129.1 PR137.1 PR142.1 PR182.2 PU8.1 PU10.1 PU11.6 PU11.21 PU11.22 PU11.23 PU11.24 PU11.25 PU11.43 PU11.46 PU11.47 PU11.48 PU11.49 PU11.50 PU11.51 PU11.56 PU11.57 R106.1 R107.1
GND: C4.1 C5.2 C7.2 C16.1 C17.2 C18.2 C19.1 C20.1 C21.1 C22.2 C23.2 C27.2 C30.1 C32.2 C33.2 C34.1 C37.2 C38.2 C41.2 C42.1 C43.1 C44.2 C45.2 C46.1 C47.1 C50.2 C51.2 C52.2 C55.1 C56.2 C57.2 C58.2 C59.2 C60.2 C61.2 C62.2 C71.2 C72.2 C73.2 C74.1 C75.1 C78.2 C79.2 C80.2 C82.1 C83.1 C84.1 C85.2 C86.2 C87.1 C89.2 C90.1 C91.2 C92.1 C94.1 C95.2 C96.2 C97.2 C98.2 C101.1 C102.2 C105.2 C106.2 C107.2 C108.2 C115.2 C118.2 C119.2 C125.2 C126.2 C131.2 C132.2 C133.2 C134.2 C135.2 C136.2 C137.2 C138.2 C139.2 C140.1 C141.1 C142.1 C143.2 C144.2 C145.2 C146.1 C147.2 C148.1 C149.1 C151.1 C156.1 C157.1 C158.1 C161.2 C162.1 C164.1 C165.1 C167.1 C170.1 C171.2 C172.1 C173.1 C174.1 C175.1 C176.1 C178.1 C179.1 C180.1 C181.1 C182.2 C183.2 C184.1 C185.1 C186.1 C187.2 C188.1 C189.1 C190.2 C191.2 C192.2 C193.2 C194.1 C195.1 C196.2 C197.2 C198.1 C199.1 C200.1 C202.1 C203.2 C204.2 C205.1 C206.1 C207.1 C208.1 C209.2 C210.2 C211.2 C214.1 C215.2 C216.2 C217.1 C218.1 C219.2 C220.1 C221.1 C222.1 C223.1 C224.1 C225.1 C226.1 C227.2 C228.2 C229.1 C230.1 C231.1 C232.2 C233.2 C234.1 C235.2 C236.2 C237.1 C238.1 C239.2 C240.1 C241.1 C242.1 C243.1 C244.1 C245.1 C246.1 C247.1 C248.1 C249.1 C250.1 C251.2 C252.2 C253.2 C254.1 C255.2 C256.2 C257.1 C258.1 C259.2 C260.2 C261.2 C262.2 C263.2 C264.2 C265.1 C266.2 C267.2 C268.1 C270.2 C271.1 C272.1 C273.2 C274.1 C275.1 C276.1 C277.1 C278.2 C279.2 C282.2 C284.1 C288.2 C290.1 C292.1 C293.1 C294.2 C295.1 C296.2 C298.2 C299.2 C300.2 C301.2 C302.2 C303.2 C304.2 C305.2 C307.2 C308.2 C309.2 C310.2 C311.2 C314.2 C315.2 C316.2 C317.2 C318.2 C319.2 C320.2 C321.1 C322.2 C323.2 C324.2 C325.2 C326.2 C327.2 C328.2 C329.1 C330.1 C331.2 C332.2 C333.1 C335.2 C336.2 C338.1 C339.1 C340.2 C341.2 C343.1 C350.1 C351.2 C355.2 C356.1 C357.2 C358.1 C359.1 CN4.3 CN4.6 CN4.12 CN4.13 CN6.4 CN6.7 CN6.10 CN6.11 CN6.12 CN6.13 CN7.2 CN7.5 CN7.8 CN7.11 CN7.17 CN7.20 CN7.21 CN7.22 CN7.23 CN8.4 CN8.5 CN8.6 CN8.7 CN8.8 CN10.4 CN10.9 CN10.15 CN10.18 CN10.21 CN10.26 CN10.27 CN10.29 CN10.34 CN10.35 CN10.37 CN10.40 CN10.43 CN10.50 CN10.53 CN10.54 CN14.1 CN14.4 CN14.7 CN14.11 CN14.12 CN14.13 CN14.17 CN14.19 CN14.23 CN14.24 CN15.2 CN16.13 CN16.16 CN16.19 CN16.22 CN16.25 CN16.28 CN16.31 CN16.32 CN16.33 CN16.34 CN17.25 CN17.26 CN18.4 CN18.9 CN18.10 CP6.2 CP6.4 CP6.6 CP6.8 CP7.2 CP7.4 CP7.6 CP7.8 CP8.2 CP8.4 CP8.6 CP8.8 CP9.2 CP9.4 CP9.6 CP9.8 CP10.2 CP10.4 CP10.6 CP10.8 CP11.2 CP11.4 CP11.6 CP11.8 D6.2 D7.2 D8.2 D15.2 D33.2 D34.2 G6.2 G7.2 HOLE7.1 HOLE7.2 HOLE7.3 HOLE7.4 HOLE7.5 HOLE7.6 HOLE7.7 HOLE7.8 HOLE7.9 HOLE7.10 HOLE8.1 HOLE8.2 HOLE8.3 HOLE8.4 HOLE8.5 HOLE8.6 HOLE8.7 HOLE8.8 HOLE8.9 HOLE10.1(PIN1) HOLE11.1(PIN1) HOLE12.1 HOLE12.2 HOLE12.3 HOLE12.4 HOLE12.5 HOLE12.6 HOLE12.7 HOLE12.8 HOLE12.9 HOLE13.1(PIN1) HOLE14.1 HOLE14.2 HOLE14.3 HOLE14.4 HOLE14.5 HOLE15.1 HOLE15.2 HOLE15.3 HOLE15.4 HOLE15.5 HOLE15.6 HOLE15.7 HOLE15.8 HOLE15.9 HOLE16.1 HOLE16.2 HOLE16.3 HOLE16.4 HOLE16.5 HOLE16.6 HOLE16.7 HOLE16.8 HOLE16.9 HOLE17.1(PIN1) HOLE18.1(PIN1) HOLE19.1 HOLE19.2 HOLE19.3 HOLE19.4 HOLE19.5 HOLE19.6 HOLE19.7 HOLE19.8 HOLE19.9 JDIM6.2 JDIM6.3 JDIM6.8 JDIM6.9 JDIM6.13 JDIM6.14 JDIM6.19 JDIM6.20 JDIM6.25 JDIM6.26 JDIM6.31 JDIM6.32 JDIM6.37 JDIM6.38 JDIM6.43 JDIM6.44 JDIM6.48 JDIM6.49 JDIM6.54 JDIM6.55 JDIM6.60 JDIM6.61 JDIM6.65 JDIM6.66 JDIM6.71 JDIM6.72 JDIM6.127 JDIM6.128 JDIM6.133 JDIM6.134 JDIM6.138 JDIM6.139 JDIM6.144 JDIM6.145 JDIM6.150 JDIM6.151 JDIM6.155 JDIM6.156 JDIM6.161 JDIM6.162 JDIM6.167 JDIM6.168 JDIM6.172 JDIM6.173 JDIM6.178 JDIM6.179 JDIM6.184 JDIM6.185 JDIM6.189 JDIM6.190 JDIM6.195 JDIM6.196 JDIM6.205 JDIM6.206 L14.1 MR6.3 PC6.2 PC7.2 PC8.2 PC9.2 PC10.1 PC12.1 PC13.2 PC14.2 PC15.1 PC17.1 PC18.2 PC19.2 PC20.2 PC21.2 PC22.2 PC23.2 PC24.2 PC25.1 PC26.1 PC27.1 PC28.2 PC29.1 PC31.2 PC32.2 PC33.1 PC34.1 PC35.2 PC36.1 PC37.2 PC38.1 PC39.1 PC40.1 PC41.1 PC42.1 PC43.1 PC44.1 PC45.2 PC46.2 PC48.2 PC50.2 PC51.2 PC52.2 PC53.2 PC54.2 PC55.2 PC56.2 PC57.1 PC58.2 PC59.2 PC60.2 PC62.2 PC63.2 PC64.2 PC65.2 PC66.2 PC67.2 PC68.1 PC69.2 PC70.1 PC72.1 PC73.1 PC74.2 PC75.1 PC76.2 PC77.2 PC78.2 PC79.2 PC80.2 PC81.2 PC85.1 PC86.2 PC87.2 PC92.2 PC93.1 PC94.2 PC95.2 PC96.2 PC97.2 PC98.2 PC99.2 PC100.2 PC101.2 PC103.2 PC106.2 PC107.2 PC109.2 PC112.1 PC113.2 PC114.2 PC115.2 PC116.1 PC118.2 PC119.1 PC120.2 PC121.2 PC122.2 PC126.2 PC127.2 PC129.1 PC130.2 PC131.2 PC132.1 PC133.2 PC134.2 PC135.2 PC137.2 PC139.2 PC140.2 PC142.1 PC143.2 PC145.1 PC146.1 PC147.1 PC148.2 PC149.2 PC150.2 PC151.2 PC152.2 PC153.2 PC154.1 PC155.1 PC156.2 PC157.2 PC158.1 PC159.2 PC160.2 PC161.2 PC162.2 PC163.1 PC164.2 PC165.2 PC166.2 PC167.1 PC168.1 PC169.1 PC170.2 PC171.2 PC172.2 PC173.1 PC174.1 PC175.2 PC176.1 PC177.2 PC178.1 PC179.2 PC180.2 PC181.1 PC182.2 PC183.1 PC184.2 PC185.2 PC186.2 PC187.1 PC188.1 PC189.2 PC190.2 PC191.2 PC192.2 PC193.2 PC194.1 PC196.1 PC197.2 PC198.2 PC199.1 PC200.1 PC201.2 PC202.2 PC203.2 PC204.1 PC205.2 PD6.2 PD11.2 PD12.2 PJ6.1 PJ6.3 PJ6.4 PJ6.5 PJ6.6 PJ6.7 PJ7.1 PJ7.2 PJ7.9 PJ7.10 PQ6.5 PQ6.6 PQ6.7 PQ7.5 PQ7.6 PQ7.7 PQ8.1 PQ8.2 PQ8.3 PQ12.1 PQ15.1 PQ18.1 PQ20.1 PQ21.1 PQ22.1 PQ23.1 PQ24.1 PQ25.1 PQ26.1 PQ27.1 PQ33.1 PQ36.1 PQ37.1 PR8.1 PR14.1 PR17.1 PR18.2 PR29.2 PR37.2 PR45.1 PR46.1 PR48.2 PR50.1 PR60.2 PR62.1 PR106.1 PR111.2 PR119.2 PR122.2 PR130.2 PR136.2 PR138.1 PR143.2 PR145.2 PR151.1 PR164.2 PR171.2 PR177.2 PU6.11 PU7.11 PU8.2 PU9.4 PU9.7 PU9.10 PU9.21 PU10.2 PU11.28 PU11.29 PU11.30 PU12.33 PU13.2 PU14.8 PU14.9 PU15.4 PU15.5 PU15.6 PU16.21 Q13.1 Q14.1 Q15.1 Q17.2 Q24.1 Q24.4 Q27.1 Q28.1 Q32.1 Q32.4 Q33.1 Q34.1 Q35.1 Q36.1 Q42.1 Q45.1 Q46.1 Q46.4 Q50.1 Q50.4 Q51.1 Q51.4 Q53.1 Q53.4 R21.1 R23.1 R25.1 R26.1 R49.1 R51.1 R54.2 R55.1 R58.1 R64.2 R70.1 R97.1 R111.1 R114.1 R146.2 R154.2 R171.2 R181.2 R220.1 R221.2 R234.2 R247.1 R248.2 R249.2 R250.1 R254.2 R255.2 R258.1 R261.2 R262.2 R270.1 R271.2 R272.2 R276.1 R284.2 R285.1 R286.1 R293.1 R299.1 R308.1 R312.2 R314.2 R320.2 R324.2 R327.1 R329.2 R336.1 R339.1 R342.2 R343.2 R347.1 R348.2 R349.1 R351.1 R355.2 R358.1 R360.2 R362.1 R368.2 R372.1 R377.1 R387.2 R389.2 R392.2 R393.2 R399.2 R414.2 SW6.2 SW6.4 SW6.5 SW6.6 SW8.2 SW8.4 SW8.5 SW8.6 T2.2 T3.2 T10.2 T11.2 T12.2 T13.2 T14.2 T15.2 U3.1 U3.3 U7.5 U9.4 U9.49 U11.33 U12.A3 U12.A5 U12.A6 U12.A11 U12.A15 U12.A19 U12.A23 U12.A27 U12.A31 U12.A35 U12.A39 U12.A43 U12.A47 U12.A49 U12.A51 U12.A52 U12.AA1 U12.AA3 U12.AA16 U12.AA19 U12.AA21 U12.AA32 U12.AA35 U12.AA38 U12.AA53 U12.AB4 U12.AB6 U12.AB10 U12.AB41 U12.AB45 U12.AB47 U12.AB48 U12.AB50 U12.AB51 U12.AC16 U12.AC18 U12.AC19 U12.AC21 U12.AC25 U12.AC33 U12.AC35 U12.AC36 U12.AC38 U12.AD7 U12.AD19 U12.AD21 U12.AD25 U12.AD32 U12.AD33 U12.AD47 U12.AE1 U12.AE3 U12.AE4 U12.AE6 U12.AE8 U12.AE9 U12.AE11 U12.AE12 U12.AE14 U12.AE40 U12.AE42 U12.AE43 U12.AE45 U12.AE46 U12.AE48 U12.AE50 U12.AE51 U12.AE53 U12.AF10 U12.AF12 U12.AF25 U12.AF32 U12.AF47 U12.AG16 U12.AG25 U12.AG36 U12.AG38 U12.AH2 U12.AH3 U12.AH4 U12.AH6 U12.AH7 U12.AH9 U12.AH41 U12.AH45 U12.AH47 U12.AH48 U12.AH50 U12.AH51 U12.AJ1 U12.AJ3 U12.AJ16 U12.AJ21 U12.AJ25 U12.AJ27 U12.AJ29 U12.AJ30 U12.AJ32 U12.AJ33 U12.AJ35 U12.AJ38 U12.AJ53 U12.AK10 U12.AK14 U12.AK16 U12.AK33 U12.AK41 U12.AK44 U12.AM2 U12.AM3 U12.AM7 U12.AM12 U12.AM19 U12.AM24 U12.AM25 U12.AM29 U12.AM33 U12.AM35 U12.AM36 U12.AM40 U12.AM44 U12.AM51 U12.AN1 U12.AN3 U12.AN5 U12.AN6 U12.AN8 U12.AN9 U12.AN11 U12.AN12 U12.AN14 U12.AN16 U12.AN22 U12.AN33 U12.AN35 U12.AN36 U12.AN38 U12.AN40 U12.AN42 U12.AN43 U12.AN45 U12.AN46 U12.AN48 U12.AN49 U12.AN51 U12.AN53 U12.AP40 U12.AT4 U12.AT12 U12.AT16 U12.AT19 U12.AT24 U12.AT27 U12.AT30 U12.AT35 U12.AT38 U12.AT47 U12.AT52 U12.AU1 U12.AU3 U12.AU24 U12.AU30 U12.AU38 U12.AU51 U12.AV7 U12.AV12 U12.AV13 U12.AV14 U12.AV18 U12.AV19 U12.AV24 U12.AV27 U12.AV30 U12.AV35 U12.AV38 U12.AV47 U12.AV51 U12.AW3 U12.AW13 U12.AW19 U12.AW27 U12.AW35 U12.AY4 U12.AY9 U12.AY10 U12.AY22 U12.AY32 U12.AY36 U12.AY50 U12.B2 U12.B52 U12.B53 U12.BA14 U12.BA19 U12.BA22 U12.BA27 U12.BA32 U12.BA35 U12.BA40 U12.BA53 U12.BB5 U12.BB7 U12.BB10 U12.BB19 U12.BB27 U12.BB35 U12.BC1 U12.BC2 U12.BC10 U12.BC20 U12.BC22 U12.BC26 U12.BC28 U12.BC32 U12.BC34 U12.BC42 U12.BD19 U12.BD24 U12.BD27 U12.BD30 U12.BD35 U12.BE1 U12.BE2 U12.BE8 U12.BE19 U12.BE35 U12.BE53 U12.BF4 U12.BF12 U12.BF16 U12.BF24 U12.BF30 U12.BF36 U12.BF38 U12.BG1 U12.BG31 U12.BG34 U12.BG39 U12.BG42 U12.BG45 U12.BG49 U12.BG53 U12.BH1 U12.BH2 U12.BH52 U12.BH53 U12.BJ2 U12.BJ3 U12.BJ5 U12.BJ7 U12.BJ11 U12.BJ15 U12.BJ19 U12.BJ23 U12.BJ27 U12.BJ31 U12.BJ35 U12.BJ39 U12.BJ43 U12.BJ47 U12.BJ49 U12.BJ51 U12.BJ52 U12.C1 U12.C14 U12.C31 U12.C34 U12.C39 U12.C42 U12.C45 U12.C49 U12.C53 U12.D12 U12.D16 U12.D24 U12.D30 U12.D36 U12.D38 U12.E1 U12.E8 U12.E19 U12.E35 U12.E53 U12.F2 U12.F5 U12.F7 U12.F19 U12.F24 U12.F27 U12.F30 U12.F35 U12.G10 U12.G20 U12.G22 U12.G26 U12.G28 U12.G32 U12.G34 U12.G42 U12.H19 U12.H27 U12.H35 U12.J1 U12.J16 U12.J19 U12.J22 U12.J27 U12.J32 U12.J35 U12.J40 U12.J53 U12.K4 U12.K9 U12.K14 U12.K22 U12.K32 U12.K36 U12.K50 U12.L13 U12.L19 U12.L27 U12.L35 U12.M19 U12.M26 U12.M27 U12.M28 U12.M34 U12.M35 U12.M38 U12.M47 U12.M51 U12.N1 U12.N16 U12.N38 U12.N51 U12.P4 U12.P9 U12.P13 U12.P16 U12.P19 U12.P20 U12.P24 U12.P32 U12.P35 U12.P38 U12.P47 U12.P52 U12.T40 U12.U1 U12.U3 U12.U5 U12.U6 U12.U8 U12.U9 U12.U11 U12.U12 U12.U14 U12.U16 U12.U21 U12.U30 U12.U32 U12.U40 U12.U42 U12.U43 U12.U45 U12.U46 U12.U48 U12.U49 U12.U51 U12.U53 U12.V7 U12.V12 U12.V16 U12.V19 U12.V21 U12.V35 U12.V40 U12.V44 U12.V51 U12.Y7 U12.Y9 U12.Y10 U12.Y14 U12.Y16 U12.Y21 U12.Y25 U12.Y33 U12.Y41 U12.Y44 U13.29 U16.4 U16.11 U16.18 U16.25 U18.5 U18.18 U18.45 U18.78 U18.89 U18.116 U19.2 U21.2 U21.5 U22.4 U24.2 U25.2 U26.2 U27.1 U30.AA4 U30.AA6 U30.K4 U30.M7 U30.P5 U30.R10 U30.U8 U30.Y2 U30.Y5 VC6.2 Y6.2 Y6.4 Y8.2 Y8.4 Y9.2 Y9.4
V1P8_AA18_PEW: C170.2 R244.1 U12.AA18
V1P8_S5_PWR: C199.2 C200.2 C205.2 C207.2 R282.1 U12.N20 U12.U24 U12.U25 U12.V25
VCC_AXG_SENSE: PR78.1 R236.2 U12.BB8
VCC_POR#: R366.1 U18.85
VCC_SENSE: PR100.1 R296.2 U12.P28
VCCRTC_1: D36.1 R412.2
VCCRTC_2: CN15.1 Q39.1 R412.1
VCCRTC_3: Q39.3 R418.2
VCCRTC_4: R417.2 R418.1
VCCSPI: C284.2 R357.2 U18.88
VDD10: C180.2 C182.1 C186.2 C196.1 C203.1 C204.1 C211.1 C227.1 L13.2 U11.3 U11.8 U11.22 U11.30
VDD_3V3_MIC1: C16.2 C19.2 L1.1 R34.1 U3.6
VDDI_DSC: C272.2 U30.K2
VDDREG/VDD33: C184.2 C195.2 R278.2 U11.23
VSS_AD18_AD16_PWR: C181.2 R272.1 U12.AD16 U12.AD18
VSS_AXG_SENSE: PR110.1 R290.1
VSS_SENSE: PR105.1 R290.2 R314.1 U12.N28
554EN_1.0V: PC36.2 PR126.1 PU6.5
554EN_1.8V: PC38.2 PR32.2 PU7.5
554FB_1.0V: PC138.1 PR120.2 PR122.1 PU6.6
554FB_1.0V_S: PC138.2 PR114.1 PR120.1
554FB_1.8V: PC30.1 PR27.2 PR29.1 PU7.6
554FB_1.8V_S: PC30.2 PR26.1 PR27.1
554LX_1.0V: PL9.1 PR34.1 PU6.1 PU6.2 PU6.3
554LX_1.8V: PL8.1 PR33.1 PU7.1 PU7.2 PU7.3
554NC_1.0V: PC29.2 PU6.7
554NC_1.8V: PC26.2 PU7.7
554PG_1.0V: PR128.2 PU6.4
554PG_1.8V: PR35.2 PU7.4
554SVIN_1.0V: PC25.2 PR24.2 PU6.8
554SVIN_1.8V: PC27.2 PR25.2 PU7.8
670AGND: PC47.1 PR145.1 PU8.14
671AGND: PR53.2 PR164.1 PU10.14
8002LX1.05V: PL14.1 PU13.3
8690_CLK: PR66.2 PU11.7
8690_DATA: PR67.2 PU11.8
8690AGND: PC82.1 PC84.2 PC88.2 PC89.1 PR59.2 PR62.2 PR64.2 PU11.5 PU11.35 PU11.42 PU11.44 PU11.45 PU11.54 PU11.55
51216DRVH: PQ9.4 PU9.14
51216DRVL: PQ8.4 PU9.11
51216MODE: PR45.2 PU9.19
51216PG: PR44.2 PU9.20
51216REFIN: PC62.1 PR48.1 PR158.2 PU9.8
51216S3: PC63.1 PR159.2 PU9.17
51216S5: PC67.1 PR162.2 PU9.16
51216SW: PC71.2 PL13.1 PQ8.5 PQ9.1 PQ9.2 PQ9.3 PR167.2 PU9.13
51216TRIP: PR46.2 PU9.18
95833_BOOT1: PR109.1 PU12.16
95833_BOOTG: PR92.1 PU12.26
95833_COMP: PC128.2 PC136.2 PR18.1 PU12.14
95833_COMPG: PC16.2 PC105.2 PR14.2 PU12.28
95833_ISUMN: PC124.2 PC125.2 PC134.1 PR13.1 PR20.2 PR89.2 PR116.1 PR117.1
95833_ISUMNG: PC99.1 PC104.2 PC110.2 PR9.1 PR75.2 PR83.2 PR84.2 PR88.2
95833_ISUMP: PC124.1 PC125.1 PC126.1 PR19.1 PR20.1 PR91.2 PU12.10
95833_ISUMPG: PC100.1 PC104.1 PC110.1 PR74.2 PR82.1 PR84.1 PU12.32
95833_LGATE1: PQ7.8 PU12.19
95833_LGATEG: PQ6.8 PU12.23
95833_NTC: PR15.2 PR16.2 PU12.7
95833_NTCG: PR6.2 PR7.2 PU12.1
95833_PHASE1: PC117.2 PL7.1 PQ7.9 PR85.1 PU12.18
95833_PHASEG: PC111.2 PL6.1 PQ6.9 PR77.1 PU12.24
95833_UGATE1: PQ7.1 PU12.17
95833_UGATEG: PQ6.1 PU12.25
+BATCHG: PC193.1 PC194.2 PD9.2 PJ7.7 PJ7.8 PR55.2 PR57.2
+LCDVCC: C73.1 C74.2 C83.2 C84.2 C85.1 CN16.6 CN16.7 CN16.8 U21.1
+SMDDR_VREF_DIMM: C318.1 C328.1 JDIM6.126 R397.2 R399.1 R401.1
+SMDDR_VREF_DQ: R388.2 R390.1 R392.1 R396.2
+SMDDR_VREF_DQ0: C302.1 C305.1 JDIM6.1 R390.2
+TPVDD: PC156.1 PC199.2 PQ38.1 PR181.2 R407.1 R527.1
+TPVDD_1: C331.1 CN18.1 Q41.2 R404.2 R405.1 R406.1 R407.2 R408.2 R411.2 R426.1 R523.2 R534.2
+VA: PC93.2 PD6.1 PD8.2 PJ6.2 PR61.1 PR71.1 PR72.2
+VA_IACM: C127.2 C128.1 C350.2 PC91.2 PQ10.4 PR71.2 PR73.2
+VAD: PC90.2 PQ10.3 PU11.11 PU11.12 PU11.13 PU11.14 PU11.15
+VAD_LD: PD8.1 PD9.1 PR69.1 PR185.2
+VSDIO: C240.2 PC201.1 PC202.1 PC203.1 PC205.1 PQ29.1 PQ30.1 R233.1 R545.1 R546.1 R547.1 R548.1 R549.1 U12.AN27
AC_PRESENT: Q24.6 R289.1 U12.D20
AC_PRESENT_EC: R281.2 U18.104
AC_PRESENT_NM: Q24.2 R281.1
ACIN: PC84.1 PR59.1 PU11.36 U18.64
ACZ_BCLK: R109.1 U12.BJ21
ACZ_RST#: R110.1 U12.BG22
ACZ_RST#_AUDIO: Q11.1 R110.2 R124.1 U9.11
ACZ_RST#_AUDIO_R: D31.1 Q11.3 R101.1
ACZ_SDIN: R65.2 U9.8
ACZ_SDIN0: R65.1 U12.BG19
ACZ_SDOUT: R103.1 U12.BG20
ACZ_SDOUT_AUDIO: R103.2 U9.5
ACZ_SPKR: D19.2 U12.BH12
ACZ_SYNC: R102.1 U12.BH20
ACZ_SYNC_AUDIO: R102.2 U9.10
ADOGND: C24.1 C27.1 C31.1 C35.2 C36.2 C37.1 C39.2 C48.1 C49.2 C53.1 C68.1 C69.2 C70.2 C337.1 C342.2 C343.2 C347.1 CN11.7 CN11.8 D11.1 D14.1 D17.1 D18.1 D20.1 D37.1 HOLE22.1 Q7.1 Q7.4 R21.2 R23.2 R25.2 R26.2 R45.2 R47.2 R53.1 R552.1 U9.25 U9.38
ALERT#: TP6.1 U7.6
AMP_MUTE#: D32.1 U18.124
BATDIS_G: PC90.1 PC91.1 PQ10.1 PR70.1
BATLED0#: R193.2 U18.65
BATLED1#: R194.2 U18.66
BATT_EN#: PJ7.6 PR177.1
BEEP_1: C40.2 C41.1 R51.2 R52.1
BIOS_STRAP: R312.1 R317.2 U12.BA30
BIT_CLK_AUDIO: C55.2 R109.2 U9.6
BL#: Q34.3 Q36.2 R385.2 R522.2
BLON_CON: CN16.14 D35.2 Q35.3 Q36.3 R371.2 R521.1
BOARD_ID1: R44.2 R54.1 U12.C13
BOARD_ID2: CN16.30 R41.2 R64.1 U12.A13
BOARD_ID3: R85.2 R271.1 U12.C19
BRIGHT: CN16.15 R277.2
BRTC_EXTPAD: C45.1 U12.B8
BT_POWERON: Q13.2 U18.114
BT_PWRON: Q13.3 R196.1 R200.1
C_TX0_HDMI+: C13.2 CN7.7 R213.2
C_TX0_HDMI-: C12.2 CN7.9 R212.2
C_TX1_HDMI+: C11.2 CN7.4 R211.2
C_TX1_HDMI-: C10.2 CN7.6 R210.2
C_TX2_HDMI+: C9.2 CN7.1 R209.2
C_TX2_HDMI-: C8.2 CN7.3 R208.2
C_TXC_HDMI+: C15.2 CN7.10 R215.2
C_TXC_HDMI-: C14.2 CN7.12 R214.2
CARD_ON_OFF: TP44.1 U18.27
CBST1: PC83.1 PD7.1 PR54.2
CCD_PWR: C82.2 C86.1 CN16.9 R122.1
CHG_BST: PR54.1 PU11.26
CHG_CEN: PR64.1 PR65.2 PU11.4
CHG_LX: PC83.2 PL12.2 PR56.2 PU11.27 PU11.33 PU11.34 PU11.41 PU11.52 PU11.53
CHG_VAC: PC85.2 PR69.2 PU11.40
CHG_VBATT: PC76.1 PC81.1 PL12.1 PR55.1 PR58.2 PU11.16 PU11.17 PU11.18 PU11.19 PU11.20
CHG_VDDP: PC82.2 PD7.2 PU11.32
CLK_24M_DEBUG: R205.1 R274.1
CLK_24M_KBC: R90.1 U18.2
CLK_PCIE_LANN: U11.16 U12.AK4
CLK_PCIE_LANP: U11.15 U12.AK6
CLK_PCIE_WLAN_REQ#_R: CN10.7 Q19.3 R231.2 R537.2
CLK_PCIE_WLANN: CN10.11 U12.AF9
CLK_PCIE_WLANP: CN10.13 U12.AF7
CLKRUN#: R279.1 R533.1 U18.8
CODEC_JDREF: R45.1 U9.15
CODEC_VREF: C53.2 U9.28
CORE_PWROK: R49.2 R56.1 R57.2 U12.B7
CORE_V1P05: R333.2 U12.AC32 U12.Y32
CORE_V1P05_S3_PW: C246.2 C247.2 C249.2 C250.2 R332.1 U12.AA33 U12.AF33 U12.AG33 U12.AG35 U12.U33 U12.U35 U12.V33
CPU_VREF: C273.1 R342.1 R344.2 U12.AF44
CPUFAN#: TP38.1 U18.22
DARM_V1P0_SOIX_PWR: C251.1 C253.1 C259.1 C262.1 R331.2 R335.2 U12.AA36 U12.AD35 U12.AF35 U12.AF36 U12.AJ36 U12.AK35 U12.AK36 U12.Y35 U12.Y36
DCAP: PC187.2 PU16.16
DDI1_DDCDATA: R303.1 U12.P30
DDI1_EDP_HPD_R: Q28.3 R307.2 U12.K30
DDI_V1P0_SOIX: C252.1 C260.1 C266.1 R325.2 U12.AJ18 U12.AK19 U12.AK21 U12.AM16
DGPU_CL_HDMIP: Q15.3 R208.1 R209.1 R210.1 R211.1 R212.1 R213.1 R214.1 R215.1
DIMM0_SA0: JDIM6.197 R393.1
DIMM0_SA1: JDIM6.201 R389.1
DMIC_CLK: T3.1 U3.4 U9.3
DMIC_DAT: T2.1 U3.5 U9.2
DNBSWON#: U18.91 U25.1
DPWROK_EC: R57.1 U18.109
DRAM_RCOMP0: R349.2 U12.AD44
DRAM_RCOMP1: R347.2 U12.AF45
DRAM_RCOMP2: R348.1 U12.AD45
DRM_PWOK_C1: Q53.5 Q53.6 R364.2
DRM_PWOK_C2: Q32.5 Q32.6 R338.2
E775AGND: C103.2 C104.1 C109.2 C110.1 L14.2 U18.103
EC_FPBACK#: Q35.2 U18.94
EC_GPIO50_SUS: PC171.1 PC172.1 PQ38.2 PU16.10
EC_PECR_R: R374.2 U18.13
EC_PWROK: Q32.2 R56.2 R375.2
EDID_PWR: CN16.10 R275.1
EDP_AUX#_C: C65.1 CN16.21 R71.2
EDP_AUX_C: C64.1 CN16.20 R70.2
EDP_TX0#_C: C67.1 CN16.18
EDP_TX0_C: C66.1 CN16.17
EEPROM_SDA: R367.1 TP54.1 U13.26
EMMC_CLK: U12.AT22 U30.W6
EMMC_CMD: R15.2 U12.AV26 U30.W5
EMMC_DATA_0: U12.AV20 U30.H3
EMMC_DATA_1: U12.AU22 U30.H4
EMMC_DATA_2: U12.AV22 U30.H5
EMMC_DATA_3: U12.AT20 U30.J2
EMMC_DATA_4: U12.AY24 U30.J3
EMMC_DATA_5: U12.AU26 U30.J4
EMMC_DATA_6: U12.AT26 U30.J5
EMMC_DATA_7: U12.AU20 U30.J6
EMMC_RCOMP: R286.2 U12.AY18
EMMC_RESET: R28.2 U12.BA24 U30.U5
EMU_LID: CN16.5 U18.82
EN_OVERRIDE: R283.2 U18.10
FANSIG: TP20.1 U18.63
G5934CN: PC195.2 PU16.19
G5934CP: PC195.1 PU16.18
G5934DISC1: PR183.2 PU16.5
G5934DISC2: PR181.1 PU16.6
G5934DISC3: PR176.1 PU16.7
G5934DISC4: PR175.2 PU16.8
G5934VIN: PC196.2 PR182.1 PR185.1 PU16.20
G5934VOUT: PC192.1 PU16.17
GPIO_NC13: R146.1 R147.2 U12.A29
GPIO_NC14: TP16.1 U12.C29
GPIO_S0_SC_56: R253.2 R254.1 U12.BC12
GPP_TX2N_LAN: C76.1 U11.18
GPP_TX2P_LAN: C77.1 U11.17
H_PROCHOT#: PC118.1 PR108.2 PU12.6 Q33.3 R130.1
HDA_RCOMP: R284.1 U12.BF20
HDMI_5V: C7.1 CN7.18 D6.1 Q17.1
HDMI_HPD: C144.1 CN7.19 Q14.2 R220.2 VC6.1
HDMI_HPD_CON: Q14.3 R206.1 U12.D27
HDMI_SCLK: CN7.15 Q6.3 R14.2
HDMI_SDATA: CN7.16 Q6.6 R11.2
HP_AGND: CN11.5 D18.2 R47.1
HP_JD#: CN11.6 D17.2 R22.2
HPL: C348.2 R66.2 R514.1 U9.32
HPL-1_TIP_SENSE: C48.2 CN11.1 D20.2 R66.1
HPR: C349.2 R27.2 R515.1 U9.33
HPR_SYS: C24.2 CN11.2 D11.2 R27.1
HWPG1.8VD: PC131.1 PQ16.4 PU16.12
HWPG_1.0V: PR128.1 R160.2
HWPG_1.5V: PR133.1 PR154.1 PU16.3 PU16.4 R382.1 U18.17
HWPG_1.05V: PR152.1 PR153.2 PR155.1 R162.2
HWPG_1.8V: PR35.1 R164.2
HWPG_1.35V: PR44.1 Q53.3 R315.2 R323.1
I2C_0_SCL: R117.1 U12.BG23
I2C_0_SDA: R108.1 U12.BH22
I2C_5_SCL: R145.1 TP34.1 U12.BG28
I2C_5_SDA: R140.1 TP33.1 U12.BH28
I2C_6_SCL: R117.2 R119.2 U27.3
I2C_6_SCL_R: CN18.6 R408.1 U27.6
I2C_6_SDA: R108.2 R118.2 U27.4
I2C_6_SDA_R: CN18.5 R404.1 U27.5
IACM: PR73.1 PU11.2
IACP: PR72.1 PU11.3
ICHM: PR57.1 PU11.39
ICHP: PR58.1 PU11.38
ICLK_DRAM_TERMN_0: R339.2 U12.AH42
ICLK_DRAM_TERMN_1: R336.2 U12.AF42
ICLK_ICOMP: R255.1 U12.AD14
ICLK_RCOMP: R261.1 U12.AD13
ICLK_USB_TERMN_0: R249.1 U12.D10
ICLK_USB_TERMN_1: R248.1 U12.F10
ICMNT: C104.2 PC87.1 PR63.1 R173.2
ICMNT_R: R173.1 U18.98
IMVP_PWRGD: PR112.2 PR123.1 PR140.2 PU12.15
IN_CLK: C15.1 R10.1 U12.AP3
IN_CLK#: C14.1 R10.2 U12.AP2
IN_D0: C13.1 R9.1 U12.AR3
IN_D0#: C12.1 R9.2 U12.AR1
IN_D1: C11.1 R8.1 U12.AT2
IN_D1#: C10.1 R8.2 U12.AT3
IN_D2: C9.1 R7.1 U12.AV3
IN_D2#: C8.1 R7.2 U12.AV2
INT_AMIC-VREFO: C49.1 R53.2 R428.2 U9.27
INT_EDP_AUXN: C65.2 U12.AK2
INT_EDP_AUXP: C64.2 U12.AK3
INT_EDP_TXN0: C67.2 U12.AG1
INT_EDP_TXP0: C66.2 U12.AG3
INTD_DSI_TE: TP17.1 U12.B30
IOAC_PCIERST#: R216.2 U18.123
ISOLATEB: R329.1 R330.2 U11.20
L_SPK+: R188.2 U9.42
L_SPK+_1: C136.1 CN19.4 R188.1
L_SPK-: R189.2 U9.43
L_SPK-_1: C137.1 CN19.3 R189.1
LAD0: R50.2 U12.BH16 U16.26 U18.126
LAD1: R46.2 U12.BJ17 U16.23 U18.127
LAD2: R40.2 U12.BJ13 U16.20 U18.128
LAD3: R32.2 U12.BG14 U16.17 U18.1
LAN_MCT0: R228.1 U8.15
LAN_MCT1: R227.1 U8.16
LAN_MCT2: R226.1 U8.21
LAN_MCT3: R225.1 U8.22
LAN_MX0+: CN9.1 U8.13
LAN_MX0-: CN9.2 U8.14
LAN_MX1+: CN9.3 U8.17
LAN_MX1-: CN9.6 U8.18
LAN_MX2+: CN9.4 U8.19
LAN_MX2-: CN9.5 U8.20
LAN_MX3+: CN9.7 U8.23
LAN_MX3-: CN9.8 U8.24
LANCT3: C28.1 R224.1 R225.2 R226.2 R227.2 R228.2
LANVCC: C91.1 C187.1 C198.2 C225.2 C228.1 C242.2 R150.1 R278.1 R298.1 R313.2 U11.11 U11.32
LFRAME#: R29.2 U12.BG17 U16.22 U18.3
LGND: C28.2 CN9.9 CN9.10 CN9.11 CN9.12 R224.2 R360.1
LID#: D33.1 D35.1 MR6.2 R359.2 U18.108
LINE1-L: C348.1 U9.22
LINE1-R: C349.1 U9.21
LINE1-VREFO-L: R514.2 U9.31
LINE1-VREFO-R: R515.2 U9.30
LPC_RCOMP: R285.2 U12.BF18
LPC_V3P3_PWR: C224.2 C235.1 C236.1 R292.2 R302.1 U12.AM27 U12.AN24
M_A_A0: JDIM6.98 U12.K45
M_A_A1: JDIM6.97 U12.H47
M_A_A2: JDIM6.96 U12.L41
M_A_A3: JDIM6.95 U12.H44
M_A_A4: JDIM6.92 U12.H50
M_A_A5: JDIM6.91 U12.G53
M_A_A6: JDIM6.90 U12.H49
M_A_A7: JDIM6.86 U12.D50
M_A_A8: JDIM6.89 U12.G52
M_A_A9: JDIM6.85 U12.E52
M_A_A10: JDIM6.107 U12.K48
M_A_A11: JDIM6.84 U12.E51
M_A_A12: JDIM6.83 U12.F47
M_A_A13: JDIM6.119 U12.J51
M_A_A14: JDIM6.80 U12.B49
M_A_A15: JDIM6.78 U12.B50
M_A_BS#0: JDIM6.109 U12.K47
M_A_BS#1: JDIM6.108 U12.K44
M_A_BS#2: JDIM6.79 U12.D52
M_A_CAS#: JDIM6.115 U12.M44
M_A_CKE0: JDIM6.73 U12.C47
M_A_CKE1: JDIM6.74 U12.F44
M_A_CLKN0: JDIM6.103 U12.M48
M_A_CLKN1: JDIM6.104 U12.P48
M_A_CLKP0: JDIM6.101 U12.M50
M_A_CLKP1: JDIM6.102 U12.P50
M_A_CS#0: JDIM6.114 U12.P44
M_A_CS#1: JDIM6.121 U12.P45
M_A_DM0: JDIM6.11 U12.G36
M_A_DM1: JDIM6.28 U12.B36
M_A_DM2: JDIM6.63 U12.F38
M_A_DM3: JDIM6.46 U12.B42
M_A_DM4: JDIM6.136 U12.P51
M_A_DM5: JDIM6.170 U12.V42
M_A_DM6: JDIM6.153 U12.Y50
M_A_DM7: JDIM6.187 U12.Y52
M_A_DQ0: JDIM6.5 U12.M36
M_A_DQ1: JDIM6.6 U12.J36
M_A_DQ2: JDIM6.18 U12.P40
M_A_DQ3: JDIM6.16 U12.M40
M_A_DQ4: JDIM6.4 U12.P36
M_A_DQ5: JDIM6.7 U12.N36
M_A_DQ6: JDIM6.15 U12.K40
M_A_DQ7: JDIM6.17 U12.K42
M_A_DQ8: JDIM6.22 U12.B32
M_A_DQ9: JDIM6.21 U12.C32
M_A_DQ10: JDIM6.34 U12.C36
M_A_DQ11: JDIM6.33 U12.A37
M_A_DQ12: JDIM6.24 U12.C33
M_A_DQ13: JDIM6.23 U12.A33
M_A_DQ14: JDIM6.35 U12.C37
M_A_DQ15: JDIM6.36 U12.B38
M_A_DQ16: JDIM6.58 U12.F36
M_A_DQ17: JDIM6.56 U12.G38
M_A_DQ18: JDIM6.67 U12.F42
M_A_DQ19: JDIM6.70 U12.J42
M_A_DQ20: JDIM6.59 U12.G40
M_A_DQ21: JDIM6.57 U12.C38
M_A_DQ22: JDIM6.68 U12.G44
M_A_DQ23: JDIM6.69 U12.D42
M_A_DQ24: JDIM6.41 U12.A41
M_A_DQ25: JDIM6.39 U12.C41
M_A_DQ26: JDIM6.51 U12.A45
M_A_DQ27: JDIM6.53 U12.B46
M_A_DQ28: JDIM6.42 U12.C40
M_A_DQ29: JDIM6.40 U12.B40
M_A_DQ30: JDIM6.52 U12.B48
M_A_DQ31: JDIM6.50 U12.B47
M_A_DQ32: JDIM6.131 U12.K52
M_A_DQ33: JDIM6.129 U12.K51
M_A_DQ34: JDIM6.140 U12.T52
M_A_DQ35: JDIM6.142 U12.T51
M_A_DQ36: JDIM6.130 U12.L51
M_A_DQ37: JDIM6.132 U12.L53
M_A_DQ38: JDIM6.143 U12.R51
M_A_DQ39: JDIM6.141 U12.R53
M_A_DQ40: JDIM6.164 U12.T47
M_A_DQ41: JDIM6.166 U12.T45
M_A_DQ42: JDIM6.176 U12.Y40
M_A_DQ43: JDIM6.177 U12.V41
M_A_DQ44: JDIM6.163 U12.T48
M_A_DQ45: JDIM6.165 U12.T50
M_A_DQ46: JDIM6.175 U12.Y42
M_A_DQ47: JDIM6.174 U12.AB40
M_A_DQ48: JDIM6.146 U12.V45
M_A_DQ49: JDIM6.148 U12.V47
M_A_DQ50: JDIM6.158 U12.AD48
M_A_DQ51: JDIM6.160 U12.AD50
M_A_DQ52: JDIM6.149 U12.V48
M_A_DQ53: JDIM6.147 U12.V50
M_A_DQ54: JDIM6.157 U12.AB44
M_A_DQ55: JDIM6.159 U12.Y45
M_A_DQ56: JDIM6.182 U12.V52
M_A_DQ57: JDIM6.183 U12.W51
M_A_DQ58: JDIM6.193 U12.AC53
M_A_DQ59: JDIM6.191 U12.AC51
M_A_DQ60: JDIM6.181 U12.W53
M_A_DQ61: JDIM6.180 U12.Y51
M_A_DQ62: JDIM6.192 U12.AD52
M_A_DQ63: JDIM6.194 U12.AD51
M_A_DQSN0: JDIM6.10 U12.K38
M_A_DQSN1: JDIM6.27 U12.B34
M_A_DQSN2: JDIM6.62 U12.F40
M_A_DQSN3: JDIM6.45 U12.C43
M_A_DQSN4: JDIM6.135 U12.M52
M_A_DQSN5: JDIM6.169 U12.T44
M_A_DQSN6: JDIM6.152 U12.Y48
M_A_DQSN7: JDIM6.186 U12.AA51
M_A_DQSP0: JDIM6.12 U12.J38
M_A_DQSP1: JDIM6.29 U12.C35
M_A_DQSP2: JDIM6.64 U12.D40
M_A_DQSP3: JDIM6.47 U12.B44
M_A_DQSP4: JDIM6.137 U12.N53
M_A_DQSP5: JDIM6.171 U12.T42
M_A_DQSP6: JDIM6.154 U12.Y47
M_A_DQSP7: JDIM6.188 U12.AB52
M_A_DRAMRST#: C321.2 JDIM6.30 U12.P41
M_A_ODT0: JDIM6.116 U12.T41
M_A_ODT1: JDIM6.120 U12.P42
M_A_RAS#: JDIM6.110 U12.M45
M_A_WE#: JDIM6.113 U12.H51
MAIND: PC182.1 PQ26.2 PQ34.4 PU16.11
MAINON: PR65.1 PR93.2 R368.1 U18.77
MBCLK: PC190.1 PD12.1 PR66.1 PR179.2 R378.1 U18.70
MBCLK2: R386.1 U7.8 U18.67
MBDATA: PC191.1 PD11.1 PR67.1 PR180.2 R384.1 U18.69
MBDATA2: R383.1 U7.7 U18.68
MDI_0+: R96.1 U11.1
MDI_0+_C: R96.2 U8.12
MDI_0-: R95.1 U11.2
MDI_0-_C: R95.2 U8.11
MDI_1+: R94.1 U11.4
MDI_1+_C: R94.2 U8.8
MDI_1-: R93.1 U11.5
MDI_1-_C: R93.2 U8.7
MDI_2+: R92.1 U11.6
MDI_2+_C: R92.2 U8.6
MDI_2-: R91.1 U11.7
MDI_2-_C: R91.2 U8.5
MDI_3+: R100.1 U11.9
MDI_3+_C: R100.2 U8.2
MDI_3-: R99.1 U11.10
MDI_3-_C: R99.2 U8.1
MIC1_INT_L: C345.2 U9.24
MIC1_INT_L_C: C345.1 R511.1
MIC1_INT_R: C344.2 U9.23
MIC1_INT_R_C: C344.1 R510.1
MIC1_INTL1: C342.1 C347.2 R428.1 R510.2 R511.2
MIC2-VREFO: R30.2 R68.2 U9.29
MIC2_MIC_RING2_MIC: C337.2 CN11.3 D37.2 R37.2
MIC2_MIC_SLEEVE_MIC: C31.2 CN11.4 D14.2 R33.2
MX0: CN17.20 CP9.7 RP6.1 U18.54
MX1: CN17.17 CP9.1 RP6.2 U18.55
